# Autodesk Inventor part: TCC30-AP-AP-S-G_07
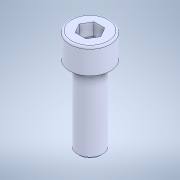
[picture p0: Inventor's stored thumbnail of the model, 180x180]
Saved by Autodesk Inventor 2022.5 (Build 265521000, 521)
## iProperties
Created: 2023-09
Part Number: TCC30-AP-AP-S-G_07
Material: 一般
Document SubType Name: Modeling
Designer: ImaoCorp
Density: 1 g/cm^3
Appearance: 既定
Author: ImaoCorp
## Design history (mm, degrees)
feature "TCC30-AP-AP-S-G_07"
node "ソリッド1"
